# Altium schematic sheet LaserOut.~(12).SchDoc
size A; DocumentNumber: 5; SheetNumber: 5; SheetTotal: 6
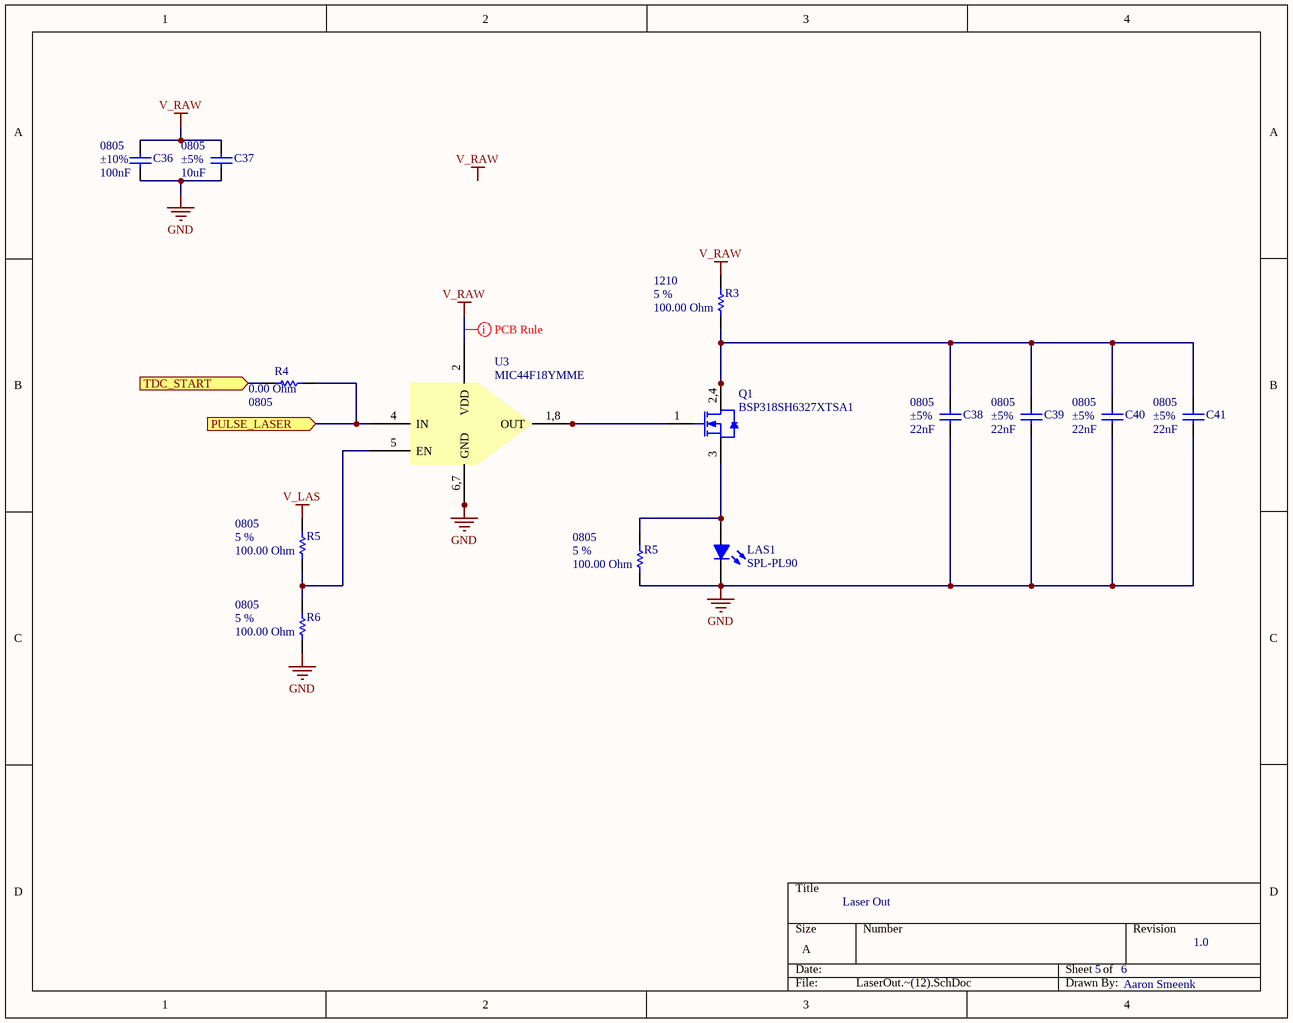
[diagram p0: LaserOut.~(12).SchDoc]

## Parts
(Parts that share a designator on the sheet are numbered #1, #2 ... from top to bottom, then left to right.)
C36  value 100nF  Case-EIA: 0805  Tolerance: ±10%  [CAPC0805(2012)100_N]  (hidden comment: CAP 100nF 6.3V 0805(2012))
C37  value 10uF  Case-EIA: 0805  Tolerance: ±5%  [CAPC0805(2012)145_N]  (hidden comment: CAP 10uF 6.3V 0805(2012))
C38  value 22nF  Case-EIA: 0805  Tolerance: ±5%  [CAPC0805(2012)100_L]  (hidden comment: CAP 22nF 6.3V 0805(2012))
C39  value 22nF  Case-EIA: 0805  Tolerance: ±5%  [CAPC0805(2012)100_L]  (hidden comment: CAP 22nF 6.3V 0805(2012))
C40  value 22nF  Case-EIA: 0805  Tolerance: ±5%  [CAPC0805(2012)100_L]  (hidden comment: CAP 22nF 6.3V 0805(2012))
C41  value 22nF  Case-EIA: 0805  Tolerance: ±5%  [CAPC0805(2012)100_L]  (hidden comment: CAP 22nF 6.3V 0805(2012))
LAS1  SPL-PL90
Q1  BSP318SH6327XTSA1  [BSP318SH6327XTSA1--SOT230P700X180-4N]
R3  value 100.00 Ohm  Tolerance: 5 %  Case-EIA: 1210  [RESC1210(3225)_L]  (hidden comment: 100R 5% 1210(3225))
R4  value 0.00 Ohm  Case-EIA: 0805  [RESC0805(2012)_N]  (hidden comment: Jumper 0805(2012))
R5#1  value 100.00 Ohm  Case-EIA: 0805  Tolerance: 5 %  [RESC0805(2012)_M]  (hidden comment: 100R 5% 0805(2012))
R5#2  value 100.00 Ohm  Case-EIA: 0805  Tolerance: 5 %  [RESC0805(2012)_M]  (hidden comment: 100R 5% 0805(2012))
R6  value 100.00 Ohm  Case-EIA: 0805  Tolerance: 5 %  [RESC0805(2012)_M]  (hidden comment: 100R 5% 0805(2012))
U3  MIC44F18YMME  [MIC44F18YMME--TSOP65P490X108_HS-9N]

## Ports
PULSE_LASER (in), TDC_START (in)

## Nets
GND: C36.1 C37.1 C38.1 C39.1 C40.1 C41.1 LAS1.2(K) R5#2.1 R6.1 U3.6(GND) U3.7(GND)
V_LAS: R5#1.2
V_RAW: C36.2 C37.2 R3.2 U3.2(VDD)
PULSE_LASER: R4.2 U3.4(IN) ; port PULSE_LASER
TDC_START: R4.1 ; port TDC_START
NetC38_2: C38.2 C39.2 C40.2 C41.2 Q1.2(D) Q1.4(D) R3.1
NetLAS1_1: LAS1.1(A) Q1.3(S) R5#2.2
NetQ1_1: Q1.1(G) U3.1(OUT) U3.8(OUT)
NetR5#1_1: R5#1.1 R6.2 U3.5(EN)

Not connected (* = marked no-connect by the designer): U3 3(NC)

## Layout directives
rule Supply Nets [Voltage = 7.400]: V_RAW

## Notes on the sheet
- Laser Out
- 5
- 6
- 1.0
- Aaron Smeenk
- Labels drawn without touching a wire or pin: V_RAW

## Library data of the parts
C36 = CMP-1036-04391-1: CAP 100nF 6.3V ±10% 0805 (2012 Metric) Thickness 1mm SMD; Case-Metric: 2012
C37 = CMP-1036-04781-1: CAP 10uF 6.3V ±5% 0805 (2012 Metric) Thickness 1.45mm SMD; Case-Metric: 2012
C38-C41 = CMP-1036-04030-1: CAP 22nF 6.3V ±5% 0805 (2012 Metric) Thickness 1mm SMD; Case-Metric: 2012
Q1 = BSP318SH6327XTSA1: MOSFET N-Ch 60V 2.6A SOT-223-3
R3 = CMP-1015-00050-1: 100R 0.5W 5% 1210 (3225 Metric)  SMD; Case-Metric: 3225
R4 = CMP-1013-00001-1: Jumper 0805 (2012 Metric); Tolerance: None; Case-Metric: 2012
R5#1 R5#2 R6 = CMP-1013-00050-1: 100R 0.125W 5% 0805 (2012 Metric)  SMD; Case-Metric: 2012
U3 = MIC44F18YMME: Gate Drivers 3A High Speed MOSFET Driver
